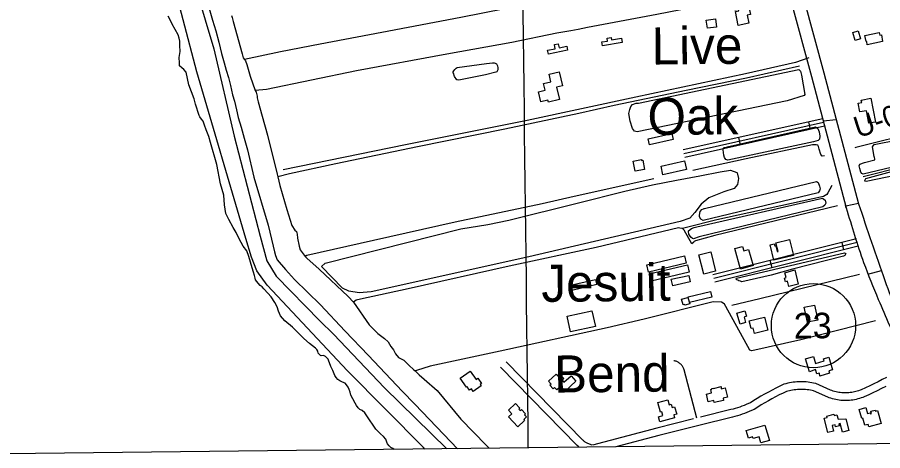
# Model space of a CAD drawing. Extents: x 3678539 to 3716648, y 451386 to 477139.
# Drawn here: x 3691344 to 3694736, y 456911 to 458608 of the extents above; entities that cross this region are included whole.
import ezdxf

# ---------------------------------------------------------------- set-up
doc = ezdxf.new("R2010")
doc.units = 0
for name, color, linetype in [('V-BLDG-OTLN', 7, 'Continuous'), ('V-GRID-FRAM', 7, 'Continuous'), ('V-GRID-MAJR', 7, 'Continuous'), ('V-LEVE-TOET', 7, 'Continuous'), ('V-RIVR-RANG-IDEN', 7, 'Continuous'), ('V-ROAD-CNTR', 7, 'Continuous'), ('V-ROAD-IDEN', 7, 'Continuous'), ('V-SITE-VEGE', 7, 'Continuous'), ('V-TOPO-GNAM-IDEN', 7, 'Continuous'), ('V-TOPO-SHOR', 7, 'Continuous')]:
    doc.layers.add(name, color=color, linetype=linetype)

msp = doc.modelspace()

# ---------------------------------------------------------------- linework, layer by layer
at = {"layer": 'V-BLDG-OTLN'}
for points in [[(3694211.9, 458584.2), (3694170.3, 458576.1), (3694159.7, 458630.4), (3694172.8, 458633), (3694171.7, 458638.6), (3694158.3, 458635.9), (3694156.3, 458646), (3694131.1, 458641), (3694128.8, 458652.9), (3694173.7, 458661.7), (3694175.4, 458653), (3694209.4, 458659.7), (3694217.5, 458618.6), (3694205.6, 458616.3)], [(3694085.4, 458569.6), (3694049.3, 458564.7), (3694044.9, 458596.7), (3694081.1, 458601.6)], [(3694648.8, 458522.8), (3694628.7, 458516.7), (3694619.3, 458547.9), (3694640.4, 458554.3)], [(3694666.4, 458536.3), (3694722.8, 458547.7), (3694724.9, 458537.3), (3694731, 458538.5), (3694736.2, 458512.7), (3694676.1, 458500.5), (3694673.5, 458513.3), (3694671.2, 458512.8)], [(3693715.2, 458509.1), (3693638.3, 458496.4), (3693635.9, 458511.1), (3693657.7, 458514.7), (3693655.8, 458526), (3693672.2, 458528.7), (3693673.8, 458519.1), (3693712.5, 458525.5)], [(3693500.8, 458479), (3693425.9, 458463.5), (3693422.8, 458478.4), (3693452.6, 458484.6), (3693449.3, 458500.6), (3693464.6, 458503.7), (3693467.7, 458488.7), (3693497.6, 458494.9)], [(3693428.7, 458384.6), (3693468.5, 458393.9), (3693481.2, 458339.9), (3693457.7, 458334.4), (3693469.1, 458285.8), (3693425.8, 458275.6), (3693424, 458283.6), (3693396.5, 458277.2), (3693387.3, 458316.5), (3693413.6, 458322.7), (3693407.4, 458349), (3693435.5, 458355.6)], [(3694652.3, 458283.6), (3694690.1, 458291), (3694708.3, 458197.7), (3694682.6, 458192.7), (3694673, 458242), (3694646.5, 458236.9), (3694639.7, 458271.8), (3694654, 458274.6)], [(3693915.4, 458129.5), (3693821.6, 458108.9), (3693816.4, 458132.4), (3693910.2, 458153.1)], [(3693803, 458012.1), (3693765.7, 458005.2), (3693758.3, 458044.9), (3693790.5, 458050.9), (3693791.1, 458047.4), (3693796.2, 458048.4)], [(3693966.8, 458012), (3693875, 457991.3), (3693867.5, 458024.9), (3693959.3, 458045.5)], [(3694371.5, 457737.2), (3694386.4, 457675.2), (3694309.6, 457656.6), (3694295.1, 457716.5), (3694311.3, 457720.4), (3694313.2, 457712.3), (3694317.6, 457713.3), (3694323.1, 457690.3), (3694326.2, 457691), (3694318.1, 457724.3)], [(3694178.9, 457621.5), (3694156.3, 457702.3), (3694186.8, 457710.8), (3694191.8, 457692.9), (3694210.7, 457698.2), (3694228.1, 457635.3)], [(3693966.1, 457644.9), (3693818.2, 457609.4), (3693811.3, 457638.1), (3693959.2, 457673.6)], [(3694062.1, 457688.8), (3694081.1, 457613), (3694034.6, 457601.4), (3694015.7, 457677.1)], [(3693978.1, 457609.2), (3693828.2, 457574), (3693821.5, 457602.8), (3693971.4, 457637.9)], [(3693982.3, 457571.5), (3693913.2, 457556.1), (3693907.5, 457581.7), (3693976.6, 457597.1)], [(3694391.5, 457619), (3694405.6, 457562.5), (3694368, 457553.1), (3694362.7, 457574.4), (3694355, 457572.4), (3694351.4, 457586.7), (3694357.8, 457588.4), (3694353, 457607.6)], [(3693615.7, 457560.9), (3693517.6, 457537.4), (3693512.7, 457558.1), (3693610.8, 457581.5)], [(3694066.8, 457512.3), (3693978.9, 457490.5), (3693973.5, 457512.5), (3694061.3, 457534.3)], [(3693972.1, 457510.9), (3693979.7, 457485.8), (3693961.4, 457480.2), (3693960.4, 457483.6), (3693954.3, 457481.7), (3693947.7, 457503.5)], [(3694469, 457480.8), (3694481.6, 457422.3), (3694441.3, 457413.6), (3694428.8, 457472.1)], [(3693596.7, 457458.2), (3693610.1, 457397.3), (3693512.8, 457376), (3693499.5, 457436.8)], [(3694165.1, 457449.3), (3694195.7, 457458.5), (3694202.3, 457436.7), (3694192.9, 457433.8), (3694199.2, 457413), (3694177.9, 457406.6)], [(3694212.8, 457419.4), (3694273.2, 457433.9), (3694285.7, 457382.1), (3694233.6, 457369.6), (3694228.5, 457390.5), (3694220.2, 457388.5)], [(3694449.1, 457219.7), (3694434.3, 457270.7), (3694464.5, 457279.5), (3694472.4, 457252.5), (3694506.6, 457262.5), (3694504.3, 457270.5), (3694524.9, 457276.5), (3694539.3, 457227.2), (3694525.6, 457223.2), (3694528.2, 457214.1), (3694490, 457202.9), (3694488.1, 457213.6), (3694478.5, 457211.1), (3694473.1, 457228.1)], [(3693080, 457195), (3693119.3, 457222.5), (3693142.4, 457189.5), (3693148.8, 457194), (3693163.1, 457173.6), (3693158, 457170), (3693162.1, 457164.1), (3693131.7, 457142.8), (3693124.9, 457152.5), (3693117.3, 457147.1), (3693108, 457160.5), (3693105.4, 457158.7)], [(3693534.1, 457182.3), (3693491.1, 457143.9), (3693474.4, 457162.5), (3693458.5, 457148.3), (3693449.5, 457158.3), (3693444.1, 457153.4), (3693432.2, 457166.7), (3693437.1, 457171), (3693426.3, 457183.1), (3693456.4, 457210), (3693463, 457202.6), (3693471, 457209.8), (3693486.2, 457192.9), (3693479.7, 457187.1), (3693486.8, 457179.1), (3693514.6, 457204)], [(3694119.4, 457156.6), (3694128.3, 457120.1), (3694110.9, 457115.9), (3694112.9, 457107.7), (3694076.1, 457098.7), (3694074, 457107.5), (3694052.7, 457102.3), (3694045.5, 457132), (3694065.5, 457136.8), (3694062.3, 457149.8), (3694066.9, 457151), (3694066.1, 457154.2), (3694072.8, 457155.8), (3694073.2, 457154.2), (3694103.7, 457162.4), (3694103.7, 457152.8)], [(3693306.6, 457003.9), (3693269.7, 457042.7), (3693282.3, 457054.7), (3693269, 457068.7), (3693297, 457095.4), (3693314, 457077.5), (3693309.7, 457073.4), (3693315.5, 457067.3), (3693320.2, 457071.8), (3693335.8, 457055.3), (3693331.7, 457051.3), (3693340.1, 457042.5), (3693330.1, 457032.9), (3693332.8, 457028.8)], [(3693855.3, 457099.1), (3693893.7, 457109.9), (3693899.3, 457090.2), (3693907.4, 457092.4), (3693910.9, 457080), (3693920.6, 457082.8), (3693928.8, 457053.8), (3693917.1, 457050.4), (3693920.1, 457039.8), (3693862.9, 457023.6), (3693857.3, 457043.6), (3693874.3, 457048.4), (3693870.2, 457062.8), (3693865.9, 457061.5)], [(3694592.2, 457035.1), (3694603.9, 456990), (3694578.3, 456983.3), (3694569.7, 457016.5), (3694564.9, 457015.3), (3694566.8, 457008.2), (3694551.3, 457004.2), (3694549.4, 457011.9), (3694538.1, 457009), (3694543.8, 456987.1), (3694521.6, 456981.3), (3694506.9, 457038.1), (3694518.5, 457041.1), (3694517.2, 457045.9), (3694545.1, 457053.1), (3694546.3, 457048.4), (3694556.9, 457051.1), (3694561.6, 457034.1)], [(3694716.6, 457067.8), (3694730.3, 457017.1), (3694682, 457004.1), (3694679.4, 457013.5), (3694666.1, 457009.9), (3694658.7, 457037.4), (3694654.4, 457036.3), (3694644.7, 457072.2), (3694670.4, 457079.2), (3694676.7, 457056.1), (3694687.6, 457059), (3694688.8, 457054.9), (3694691.8, 457055.7), (3694689.3, 457064.9), (3694707.4, 457069.8), (3694708.6, 457065.6)], [(3694274.8, 457010.2), (3694292.1, 456950.2), (3694259.3, 456940.8), (3694252.4, 456964.8), (3694228.2, 456957.8), (3694226.3, 456964.3), (3694210.2, 456959.7), (3694201.7, 456989.2)]]:
    msp.add_lwpolyline(points, close=True, dxfattribs=at)
at = {"layer": 'V-GRID-FRAM'}
msp.add_lwpolyline([(3682569.5, 474981.5), (3714284.1, 475345.9), (3714501, 457164.6), (3682770.5, 456800), (3682569.5, 474981.5)], dxfattribs=at)
at = {"layer": 'V-GRID-MAJR'}
msp.add_spline([(3693347.3, 456921.6), (3693278.6, 462978.9), (3693209.8, 469039.4), (3693141.1, 475099.9), (3693141.1, 475103)], degree=3, dxfattribs=at)
at = {"layer": 'V-LEVE-TOET'}
for points in [[(3692942.2, 456916.9), (3692936.9, 456922.5), (3692638.8, 457223.3), (3692323.7, 457559), (3692282.9, 457615.2), (3692262.7, 457668.4), (3692239.9, 457741.7), (3692048.5, 458394.3), (3691887.6, 459006.2), (3691647, 459899.5), (3691622.3, 459954.7), (3691606.9, 459977.7), (3691566.7, 459999.2), (3691518.4, 460020.5), (3691426.3, 460046.5), (3691094.8, 460147.1), (3690922.6, 460184.9), (3690402.1, 460331.4), (3689708.9, 460530.6), (3689528.4, 460590.6), (3689424.4, 460641.8), (3689390.4, 460693.6)], [(3691076.1, 460218.9), (3691417.8, 460117.3), (3691559.6, 460085.3), (3691658.3, 460041.9), (3691690.9, 460000.2), (3691710.4, 459949.2), (3691802.2, 459621.1), (3691843.7, 459475.4), (3691872.8, 459359.7), (3691899, 459256.7), (3691957.9, 459037.6), (3691966.3, 459006.5), (3692013.2, 458826.8), (3692114.6, 458483.6), (3692194, 458141.8), (3692296.6, 457750.8), (3692322.8, 457653.8), (3692359, 457593.7), (3692530.4, 457419.7), (3692583.8, 457366.7), (3692784, 457156.4), (3693027.4, 456917.9)]]:
    msp.add_lwpolyline(points, dxfattribs=at)
at = {"layer": 'V-ROAD-CNTR'}
for p, q in [((3694453, 458168.9), (3694446.4, 458198.2)), ((3694179.4, 458107.8), (3694172.9, 458137)), ((3694584.3, 457696.8), (3694577, 457725.9)), ((3694303.1, 457626.4), (3694295.8, 457655.5))]:
    msp.add_line(p, q, dxfattribs=at)
for points in [[(3694266.9, 459270.4), (3694505, 458390.6), (3694642, 457876.7)], [(3694218.5, 459254.9), (3694218.5, 459254.9), (3694456.6, 458375.3), (3694593.5, 457861.5)], [(3694447.2, 458449.2), (3694394, 458431.1), (3694199, 458386.6), (3693768.2, 458295), (3693342.2, 458203.5), (3692865.2, 458108.7), (3692385.9, 458010.9)], [(3694501.1, 458210.5), (3693954, 458088.1)], [(3694502.7, 458202.1), (3694553.7, 458207.9)], [(3694504.4, 458195.8), (3693957.3, 458073.5)], [(3694507.7, 458181.2), (3693960.5, 458058.8)], [(3694591.4, 457869.3), (3694641, 457880.3)], [(3694633.3, 457740), (3694070.8, 457599.2)], [(3694636.9, 457725.4), (3694074.4, 457584.7)], [(3694640.5, 457710.9), (3694078.1, 457570.1)], [(3694678, 457601.8), (3694731.4, 457616)], [(3693597.8, 456932.5), (3693580.9, 456938.6), (3693578.1, 456939.8), (3693575.3, 456941.1), (3693572.7, 456942.6), (3693570.1, 456944.2), (3693567.6, 456946), (3693565.2, 456947.9), (3693562.9, 456949.9), (3693560.6, 456952.3), (3693260.2, 457258.8)], [(3694008.4, 457038.1), (3693957.7, 457227.5), (3693956.7, 457230.5), (3693955.5, 457233.5), (3693954.2, 457236.3), (3693952.7, 457239.1), (3693951, 457241.8), (3693949.1, 457244.3), (3693947.1, 457246.7), (3693944.9, 457249), (3693942.6, 457251.2), (3693940.2, 457253.2), (3693937.6, 457255), (3693934.9, 457256.7), (3693932.2, 457258.2), (3693929.3, 457259.5), (3693926.3, 457260.6), (3693923.3, 457261.5), (3693920.3, 457262.3), (3693917.2, 457262.8)], [(3693547.2, 456923.8), (3693545.9, 456924.9), (3693542.4, 456928), (3693539.3, 456931.1), (3693238.7, 457237.8)], [(3694750.7, 457197.2), (3694734.5, 457188.8), (3694718.2, 457180.5), (3694701.8, 457172.4), (3694685.4, 457164.5), (3694668.8, 457156.7), (3694652.5, 457149.3), (3694647.4, 457147.2), (3694642.1, 457145.3), (3694636.7, 457143.6), (3694631.3, 457142.1), (3694625.8, 457140.8), (3694620.3, 457139.6), (3694614.8, 457138.7), (3694609.2, 457137.9), (3694603.6, 457137.4), (3694598, 457137), (3694592.3, 457136.8), (3694586.7, 457136.9), (3694581.1, 457137.1), (3694575.5, 457137.5), (3694569.9, 457138.2), (3694564.3, 457139), (3694558.8, 457140), (3694553.3, 457141.2), (3694547.8, 457142.6), (3694542.4, 457144.2), (3694537.1, 457146), (3694532, 457147.9), (3694474.1, 457173.4), (3694465.7, 457175.3), (3694458.5, 457176.7), (3694451.3, 457177.9), (3694444, 457178.8), (3694436.7, 457179.6), (3694429.4, 457180.1), (3694422.1, 457180.4), (3694414.8, 457180.4), (3694407.4, 457180.3), (3694400.1, 457179.9), (3694392.8, 457179.3), (3694385.5, 457178.5), (3694378.3, 457177.4), (3694371.1, 457176.1), (3694363.9, 457174.6), (3694356.8, 457172.9), (3694348.6, 457170.7), (3694332.5, 457163), (3694317.6, 457155.6), (3694302.8, 457148), (3694288.1, 457140.2), (3694273.6, 457132.1), (3694259.1, 457123.9), (3694244.8, 457115.4), (3694230.6, 457106.8), (3694217.5, 457098.5), (3694209.9, 457094.9), (3694201.5, 457091.3), (3694193.1, 457087.8), (3694184.6, 457084.6), (3694175.9, 457081.5), (3694167.3, 457078.7), (3694158.5, 457076.1), (3694149.7, 457073.7), (3694140.7, 457071.5), (3694022.8, 457041.7)], [(3694748.2, 457162.1), (3694731.6, 457153.7), (3694715, 457145.5), (3694698.3, 457137.4), (3694681.4, 457129.5), (3694664.3, 457121.7), (3694658, 457119.2), (3694651.7, 457116.9), (3694645.3, 457114.9), (3694638.9, 457113.1), (3694632.4, 457111.5), (3694625.9, 457110.1), (3694619.3, 457109), (3694612.7, 457108.1), (3694606, 457107.5), (3694599.4, 457107), (3694592.7, 457106.8), (3694586, 457106.9), (3694579.3, 457107.2), (3694572.7, 457107.7), (3694566, 457108.4), (3694559.4, 457109.4), (3694552.8, 457110.6), (3694546.3, 457112), (3694539.9, 457113.7), (3694533.4, 457115.6), (3694527.1, 457117.7), (3694520.7, 457120.1), (3694464.6, 457144.8), (3694459.5, 457145.9), (3694453.2, 457147.2), (3694446.9, 457148.2), (3694440.6, 457149), (3694434.2, 457149.7), (3694427.8, 457150.1), (3694421.4, 457150.4), (3694415, 457150.4), (3694408.6, 457150.3), (3694402.2, 457150), (3694395.8, 457149.4), (3694389.4, 457148.7), (3694383.1, 457147.8), (3694376.7, 457146.7), (3694370.5, 457145.4), (3694364.2, 457143.9), (3694359.1, 457142.5), (3694345.6, 457136), (3694331.1, 457128.8), (3694316.7, 457121.4), (3694302.4, 457113.8), (3694288.3, 457106), (3694274.2, 457097.9), (3694260.3, 457089.7), (3694246.4, 457081.3), (3694231.9, 457072.1), (3694222.2, 457067.6), (3694213.2, 457063.6), (3694204.1, 457059.9), (3694194.9, 457056.4), (3694185.6, 457053.1), (3694176.2, 457050.1), (3694166.8, 457047.3), (3694157.3, 457044.7), (3694147.9, 457042.4), (3694015.9, 457009), (3693858.9, 456969.4), (3693690.5, 456925.5)], [(3693995.1, 457034.7), (3693851.5, 456998.5), (3693598.2, 456932.4)]]:
    msp.add_lwpolyline(points, dxfattribs=at)
for points in [[(3694788, 460664.6), (3694854.8, 460447.7), (3694908.2, 460241.9), (3694923.9, 460065.9), (3694912.9, 459920.9), (3694867.4, 459717.8), (3694810.9, 459555), (3694731.9, 459268.4), (3694721.4, 459066.6), (3694739.2, 458851.9), (3694832.3, 458599.2), (3694993.1, 458299.7)], [(3694593.5, 457861.5), (3694593.4, 457861.7), (3694590.1, 457874.8)], [(3694641.7, 457877.7), (3694744.7, 457577.3), (3694792.5, 457453.3), (3694914.5, 457209.3), (3695069.9, 456946.6)], [(3694593.5, 457861.5), (3694661.7, 457647.7), (3694719.2, 457502.7), (3694808.7, 457304.6), (3695020.5, 456948.3)]]:
    msp.add_spline(points, degree=3, dxfattribs=at)
at = {"layer": 'V-ROAD-IDEN'}
msp.add_circle((3694465, 457400.3), 165, dxfattribs=at)
msp.add_circle((3694465, 457400.3), 165, dxfattribs=at)
at = {"layer": 'V-SITE-VEGE'}
for points in [[(3693779.2, 458271.3), (3694408, 458403.8), (3694414, 458396.2), (3694417.6, 458381.4), (3694430.5, 458305.8), (3694428.8, 458301), (3694362.1, 458280.4), (3693773.4, 458158.8), (3693764, 458161.7), (3693755, 458172.3), (3693747.1, 458201.3), (3693741.6, 458230.8), (3693745.7, 458246.2), (3693749.7, 458258.7), (3693756.2, 458266.4), (3693770.3, 458271.3)], [(3694127.1, 458100.8), (3694473.4, 458178.8), (3694482.3, 458172.3), (3694487.1, 458158.8), (3694490.2, 458142.2), (3694488.5, 458130.4), (3694483.8, 458125), (3694464.9, 458120.2), (3694129.8, 458047.6), (3694122.1, 458051.1), (3694116.7, 458058.1), (3694113.1, 458067.6), (3694111.9, 458078.2), (3694110.6, 458088.3), (3694111.8, 458093.6), (3694114.1, 458098.3), (3694124.8, 458099.6)], [(3694165.5, 457998.1), (3694171.1, 457976.1), (3694167.1, 457952.8), (3694153.5, 457937.6), (3694113.8, 457923.6), (3694054.9, 457901.3), (3694024.9, 457876.4), (3694000.4, 457843.3), (3693980, 457821.2), (3693943, 457808.6), (3693349.8, 457670.3), (3692731.9, 457533.2), (3692683.9, 457528.7), (3692644.1, 457535.3), (3692619.3, 457547.5), (3692536.4, 457632.1), (3692551.5, 457644.5), (3693082.9, 457779.7), (3693188.5, 457796.8), (3693270.7, 457813.8), (3693539.2, 457880.1), (3693725.5, 457926.6), (3693833.7, 457952), (3693928.3, 457970.4), (3694020.1, 457987.5), (3694099.6, 458003.1), (3694139.3, 458008.9), (3694164.1, 457999.4)], [(3694670.5, 457976.6), (3694885.5, 458034.8), (3694890.3, 458030.7), (3694890.3, 458025.9), (3694887.4, 458016.5), (3694867.3, 458005.1), (3694671.7, 457964.2), (3694666.4, 457966.5), (3694666.4, 457968.3), (3694667.5, 457971.8)], [(3694038.1, 457859.4), (3694477.1, 457965.2), (3694483.1, 457961.1), (3694489.1, 457946.9), (3694490.9, 457936.3), (3694489.2, 457928), (3694483.3, 457920.9), (3694033.1, 457812.6), (3694023.6, 457816.7), (3694018.2, 457826.1), (3694018.2, 457833.2), (3694020.5, 457847.4), (3694027.5, 457855.2), (3694034, 457857.6), (3694036.4, 457859.4)], [(3694007.8, 457787.6), (3694500.6, 457899.7), (3694510.8, 457892), (3694513.2, 457880.2), (3694509.1, 457871.9), (3694501.5, 457865.9), (3694017, 457747.4), (3693995.1, 457740.7), (3693991, 457741.9), (3693983.8, 457746.6), (3693976.7, 457759), (3693974.8, 457768.4), (3693975.4, 457772), (3693987.2, 457780.3), (3693997.8, 457785.1)], [(3694163, 457585.6), (3694586.7, 457686), (3694591.4, 457683.1), (3694590.3, 457679.5), (3694589.1, 457677.7), (3694587.3, 457675.4), (3694582.6, 457671.8), (3694382.3, 457620.8), (3694299.6, 457597.7), (3694184.4, 457572.1), (3694178.5, 457573.9), (3694172, 457575.6), (3694168.4, 457577.9), (3694164.2, 457579.7), (3694161.9, 457582)]]:
    msp.add_lwpolyline(points, close=True, dxfattribs=at)
msp.add_lwpolyline([(3694824, 458032.6), (3694659.7, 457993.1), (3694655, 457995.4), (3694650.8, 458001.9), (3694646.6, 458015.5), (3694644.7, 458026.7), (3694646.4, 458032.6), (3694664.7, 458038.7), (3694704.9, 458049), (3694705.5, 458053.1), (3694704.3, 458059.1), (3694703.1, 458062.6), (3694696.3, 458101), (3694703.3, 458109.3), (3694795.5, 458127.7)], dxfattribs=at)
at = {"layer": 'V-TOPO-SHOR'}
msp.add_line((3694925.6, 458050.5), (3694660.4, 457983.6), dxfattribs=at)
for points in [[(3693965.6, 458771.1), (3693715.2, 458726.3), (3693508.6, 458689), (3693420.5, 458673.1), (3693082.1, 458606.9), (3692773.1, 458547.8), (3692531.4, 458503), (3692375.4, 458472.6), (3692234.7, 458443.1)], [(3692090.5, 458659.9), (3692108.7, 458595.9), (3692122.6, 458554.4), (3692134.2, 458510), (3692145.2, 458465.5), (3692155.5, 458429.4), (3692163.4, 458400.4), (3692171.9, 458371.9), (3692179.8, 458341.1), (3692187.8, 458304.4), (3692195.1, 458278.9), (3692203, 458245.7), (3692210.3, 458215.5), (3692221.2, 458177.6), (3692234, 458134.3), (3692246.7, 458089.3), (3692271.2, 457982)], [(3694079.1, 458663), (3693851, 458619), (3693579.4, 458567.7), (3693542, 458559.4), (3693513.8, 458554.6), (3693459.1, 458545), (3693282.4, 458509.3), (3693028.1, 458463.2), (3692674.1, 458397.6), (3692320.8, 458325), (3692276.5, 458321.1)], [(3692184.3, 458614.3), (3692186.2, 458607.2), (3692190.4, 458591.2), (3692225.1, 458465), (3692229.9, 458449), (3692234.7, 458443.1), (3692238.9, 458437.2), (3692243.8, 458423), (3692256.5, 458376.8), (3692276.5, 458321.1), (3692280.7, 458314), (3692284.9, 458299.2), (3692285, 458292.1), (3692288.6, 458276.1), (3692304.4, 458221), (3692324.5, 458146.3), (3692362.3, 457994), (3692364.9, 457982.5), (3692373.3, 457948.4), (3692400.6, 457855.4), (3692420, 457792.6), (3692432, 457773.7), (3692438, 457769.5), (3692441.6, 457758.3), (3692442.3, 457742.9), (3692448.4, 457711.4), (3692453.3, 457696.6), (3692464.1, 457681.3), (3692473.1, 457671.3), (3692479, 457664.7), (3692527.4, 457621.1), (3692640.8, 457514.4), (3692662.3, 457492.6), (3692723.5, 457404), (3692757.5, 457369.8), (3692783.2, 457350.4), (3692797.5, 457337.4), (3692808.9, 457319.1), (3692819.1, 457304.9), (3692826.3, 457290.1), (3692838.9, 457275.3), (3692859.1, 457265.4), (3692879.4, 457245.9), (3692897.9, 457227.7), (3692903.1, 457222.6), (3692918.8, 457207), (3692939.1, 457190.5), (3692989.3, 457145.7), (3693083.2, 457033.6), (3693181.8, 456932.1), (3693194, 456919.8)], [(3692065.6, 458208.8), (3692059.2, 458217.4), (3692056.9, 458223.2), (3692042.2, 458268.2), (3692037.4, 458288.9), (3692016.8, 458343.1), (3692005.5, 458393.3), (3691996.8, 458403.7), (3691988.7, 458409.4), (3691980.5, 458418), (3691979.9, 458429.5), (3691978.6, 458450.3), (3691983, 458473.5), (3691981.7, 458497.7), (3691981.6, 458513.9), (3691978.7, 458525.4), (3691974.5, 458538.7), (3691951.1, 458580.2), (3691944.7, 458595.7), (3691935.9, 458611.8)], [(3694410.8, 458416.3), (3694203.1, 458370), (3693966, 458320.6), (3693683.4, 458262.3), (3693545.3, 458231.4), (3693254.7, 458169), (3692912.3, 458101.1), (3692592.4, 458033.3), (3692411.1, 457995.2), (3692364.9, 457982.5)], [(3693068.8, 458411), (3693183.3, 458426.7), (3693206.4, 458429.2), (3693213.3, 458429.2), (3693216.7, 458428.6), (3693222.5, 458425.8), (3693226, 458417.2), (3693227.8, 458410.3), (3693227.3, 458402.2), (3693223.3, 458394.1), (3693219.9, 458392.4), (3693179, 458382.9), (3693075.4, 458361.5), (3693067.9, 458362.6), (3693066.8, 458363.1), (3693058, 458376.3), (3693053.4, 458389), (3693051.6, 458392.4), (3693052.2, 458394.7), (3693055, 458398.2), (3693059.6, 458403.4), (3693064.8, 458408.6), (3693068.8, 458411)], [(3692822, 456915.5), (3692816.5, 456919.5), (3692807.8, 456922.9), (3692801.4, 456929.2), (3692795, 456937.3), (3692792.7, 456944.2), (3692789.1, 456955.1), (3692779.2, 456965.5), (3692767.6, 456976.9), (3692749, 456995.3), (3692714.6, 457046.5), (3692706.4, 457058.6), (3692695.9, 457067.8), (3692687.2, 457071.8), (3692680.3, 457078.1), (3692673.3, 457087.3), (3692668.6, 457096.5), (3692659.2, 457113.2), (3692652.2, 457128.2), (3692649.2, 457139.7), (3692645.1, 457149.5), (3692641.6, 457158.7), (3692635.2, 457168.5), (3692628.8, 457175.4), (3692618.4, 457179.4), (3692608.5, 457183.9), (3692600.4, 457189.6), (3692594, 457197.1), (3692588.2, 457205.2), (3692580.5, 457224.8), (3692573.5, 457240.3), (3692568.2, 457254.1), (3692565.8, 457261.1), (3692562.3, 457268.5), (3692551.8, 457280), (3692544.3, 457283.4), (3692535.1, 457282.2), (3692532.8, 457283.4), (3692528.7, 457286.8), (3692523.5, 457292.6), (3692521.7, 457300.1), (3692518.7, 457306.4), (3692513.5, 457312.1), (3692489.7, 457329.9), (3692467, 457350.5), (3692423.4, 457393.6), (3692393.2, 457419.4), (3692375.7, 457438.9), (3692368.1, 457456.8), (3692362.2, 457474.1), (3692353.4, 457491.4), (3692339.4, 457512.6), (3692326.1, 457527.6), (3692310.9, 457544.8), (3692303.4, 457551.7), (3692296.4, 457557.4), (3692288.2, 457566), (3692278.3, 457579.8), (3692277.1, 457585.6), (3692273.6, 457597.1), (3692270.6, 457609.8), (3692264.7, 457627.1), (3692251.7, 457671), (3692243.5, 457692.9), (3692230.1, 457711.3), (3692221.3, 457726.2), (3692212, 457742.3), (3692202, 457764.8), (3692189.8, 457784.4), (3692172.8, 457815.5), (3692161.7, 457839.1), (3692158.7, 457855.8), (3692156.8, 457873.7), (3692154.3, 457911.3), (3692140.7, 457955.7), (3692126.3, 458031.3), (3692101.5, 458117.2), (3692094.4, 458140.8), (3692089.7, 458154.1), (3692084.4, 458166.8), (3692077.9, 458185.8), (3692072.6, 458200.8), (3692065.6, 458208.8)], [(3694883.6, 458160.3), (3694631.6, 458097.6), (3694627, 458096.4)], [(3694508, 458065.6), (3694499.7, 458064.4), (3694493.3, 458070.1), (3694487.4, 458090.8), (3694484.5, 458101.2), (3694481.6, 458106.4), (3694475.2, 458108.6), (3694460.8, 458108), (3694201.3, 458053.8), (3693991.7, 458007.6)], [(3692271.2, 457982), (3692327.6, 457793.6), (3692347.1, 457711.8), (3692352, 457689.9), (3692356.3, 457675.1), (3692362.9, 457658.5), (3692395.2, 457620.7), (3692431.1, 457581.2), (3692533.2, 457481.6), (3692627.7, 457380.1), (3692720.9, 457283.9), (3692853, 457143.5), (3692902, 457092.8), (3693016.2, 456973.7), (3693070.1, 456918.4)], [(3693839.8, 457975.5), (3693526.9, 457906.5), (3693402.1, 457877.5), (3693060.8, 457804.9), (3692739.8, 457734.3), (3692479.7, 457675.5), (3692473.1, 457671.3)], [(3694537.4, 457948.9), (3694521.8, 457920.7), (3694517.2, 457913.6), (3694504.9, 457905.4), (3694086.6, 457814.7), (3693966.7, 457784.7), (3693957.3, 457781.7), (3693951.5, 457780.1)], [(3694558.7, 457868.8), (3694078.5, 457752.9), (3694003.1, 457731.9), (3693997.8, 457729.6), (3693996.1, 457726.6), (3693988.8, 457721)], [(3693988.8, 457721), (3693957.9, 457774.3), (3693951.5, 457780.1), (3693948.6, 457781.2), (3693941.7, 457782.3), (3693935.4, 457782.8), (3693613.2, 457706.4), (3693272, 457632.7), (3692876.7, 457544.9), (3692689.7, 457504.5), (3692672.4, 457499.7), (3692662.3, 457492.6)], [(3694645.4, 457601.1), (3694254.4, 457505.3), (3694144.5, 457479.2)], [(3694708.5, 457418.7), (3694415, 457344.4), (3694223.4, 457301.1), (3694215.9, 457304), (3694121.5, 457475.6), (3694116.2, 457483.7), (3694110.4, 457488.8), (3694104.1, 457491.7), (3694071.2, 457493.7), (3693801.4, 457425.1), (3693656.4, 457391.9), (3693236.4, 457300.5), (3692961.9, 457241.6), (3692909, 457225.1), (3692903.1, 457222.6)]]:
    msp.add_lwpolyline(points, dxfattribs=at)

# ---------------------------------------------------------------- texts
at = {"layer": 'V-RIVR-RANG-IDEN'}
msp.add_text('U-030', height=83, rotation=18.2623, dxfattribs=at).set_placement((3694639.3, 458134.1))
at = {"layer": 'V-ROAD-IDEN'}
msp.add_text('23', height=100, rotation=0.6583, dxfattribs=at).set_placement((3694388.1, 457349.5))
at = {"layer": 'V-TOPO-GNAM-IDEN'}
for s, p in [('Live', (3693831.2, 458422.6)), ('Oak', (3693815, 458146.6)), ('Jesuit', (3693398.9, 457493.2)), ('Bend', (3693448.8, 457138))]:
    msp.add_text(s, height=145, rotation=0.5436, dxfattribs=at).set_placement(p)

doc.saveas('drawing.dxf')
